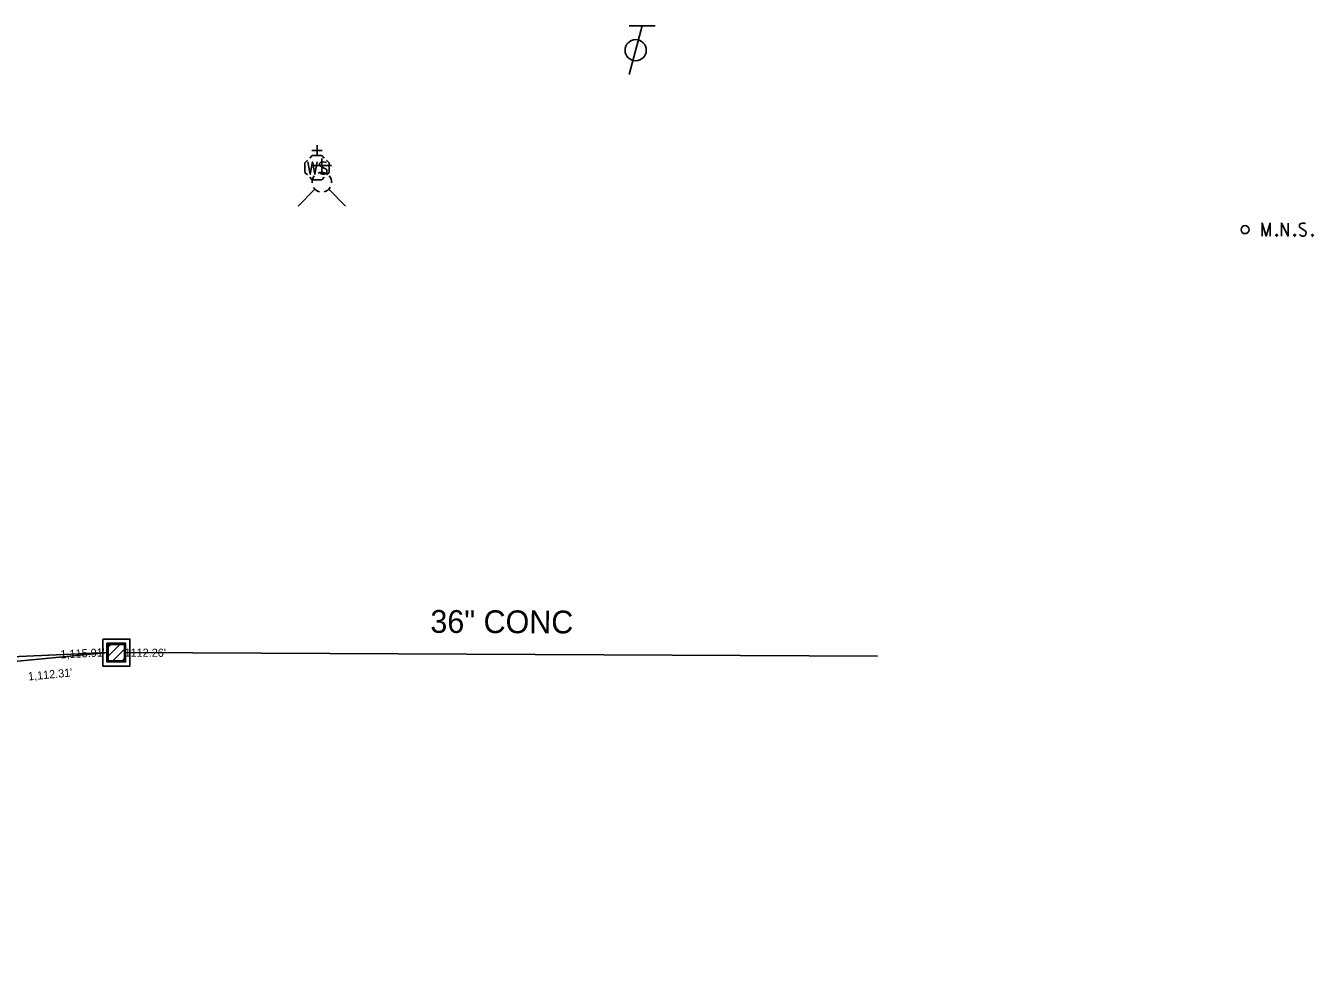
# Model space of a CAD drawing. Extents: x 146022 to 147632, y 437624 to 440659.
# Drawn here: x 147473.8 to 147632, y 438553.3 to 438669.1 of the extents above; entities that cross this region are included whole.
import ezdxf

# ---------------------------------------------------------------- set-up
doc = ezdxf.new("R2010")
doc.units = 0
for name, color, linetype in [('DR_X_Storm_Sewer', 7, 'Continuous'), ('DR_X_Text', 7, 'Continuous'), ('DT_X_Triangles', 7, 'Continuous'), ('RD_P_GR_Rt', 7, 'Continuous'), ('RW_P_Const_Limits', 7, 'Continuous'), ('SC_Scratch1', 7, 'Continuous'), ('UT_X_Electric', 7, 'Continuous'), ('UT_X_Overhead_Cable_TV', 7, 'Continuous')]:
    doc.layers.add(name, color=color, linetype=linetype)

msp = doc.modelspace()

# ---------------------------------------------------------------- linework, layer by layer
at = {"layer": 'DR_X_Storm_Sewer'}
for p, q in [((147070.7, 438553.26), (147483.94, 438592.14)), ((147428.39, 438589.62), (147483.94, 438592.14)), ((147485.94, 438592.14), (147578.45, 438591.72))]:
    msp.add_line(p, q, dxfattribs=at)
at = {"layer": 'DT_X_Triangles'}
for p, q in [((147484.94, 438593.81), (147484.94, 438593.81)), ((147483.94, 438592.14), (147483.94, 438592.14)), ((147484.94, 438593.14), (147484.94, 438593.14)), ((147484.94, 438592.14), (147484.94, 438592.14)), ((147484.94, 438592.14), (147484.94, 438592.14)), ((147484.94, 438592.14), (147484.94, 438592.14)), ((147485.94, 438592.14), (147485.94, 438592.14)), ((147484.94, 438591.14), (147484.94, 438591.14)), ((147484.94, 438590.48), (147484.94, 438590.48))]:
    msp.add_line(p, q, dxfattribs=at)
at = {"layer": 'RD_P_GR_Rt'}
for p, q in [((147510.23, 438653.81), (147508.95, 438653.81)), ((147509.59, 438653.17), (147509.59, 438654.44)), ((147511.38, 438651.96), (147508.98, 438651.96)), ((147509.59, 438651.69), (147509.59, 438651.69)), ((147510, 438651.85), (147510.7, 438651.49)), ((147510.18, 438651.1), (147510.18, 438652.82)), ((147509.34, 438649.05), (147507.26, 438646.97)), ((147510.18, 438649.9), (147510.18, 438649.9)), ((147510.18, 438649.9), (147510.18, 438649.9)), ((147511.03, 438649.05), (147513.11, 438646.97))]:
    msp.add_line(p, q, dxfattribs=at)
for points in [[(147508.42, 438652.59), (147508.11, 438652.28), (147508.11, 438651.1), (147508.41, 438650.8)], [(147508.48, 438652.4), (147508.77, 438650.87), (147509.05, 438652.4), (147509.33, 438650.87), (147509.62, 438652.4)], [(147510.49, 438652.87), (147510.18, 438653.17), (147509, 438653.17), (147508.7, 438652.87)], [(147510.77, 438650.8), (147511.07, 438651.1), (147511.07, 438652.28), (147510.77, 438652.59)], [(147508.69, 438650.52), (147509, 438650.21), (147510.18, 438650.21), (147510.49, 438650.51)]]:
    msp.add_lwpolyline(points, dxfattribs=at)
for centre, radius, start, end in [((147510.15, 438652.08), 0.271, 126.2587, 236.3676), ((147510.37, 438651.6), 0.8, 61.3463, 118.6537), ((147510.18, 438649.9), 1.2, 140.021, 184.0629), ((147510.18, 438649.9), 1.2, 68.1395, 112.038), ((147510.34, 438651.51), 0.633, 223.6695, 304.3963), ((147510.47, 438651.24), 0.339, 311.4883, 47.9358), ((147510.18, 438649.9), 1.2, 356.0165, 39.9889), ((147510.18, 438649.9), 1.2, 211.8788, 255.8479), ((147510.18, 438649.9), 1.2, 283.8239, 329.9097)]:
    msp.add_arc(centre, radius, start, end, dxfattribs=at)
at = {"layer": 'RW_P_Const_Limits'}
for points in [[(147625.68, 438643.28), (147625.68, 438644.88), (147626.19, 438643.28), (147626.67, 438644.88), (147626.67, 438643.28)], [(147628.05, 438643.28), (147628.05, 438644.88), (147628.88, 438643.28), (147628.88, 438644.88)], [(147631.03, 438644.77), (147631, 438644.79), (147630.97, 438644.82), (147630.87, 438644.86), (147630.75, 438644.88), (147630.66, 438644.88), (147630.63, 438644.88), (147630.49, 438644.84), (147630.37, 438644.77), (147630.29, 438644.67), (147630.27, 438644.57), (147630.27, 438644.49), (147630.29, 438644.39), (147630.38, 438644.3), (147630.98, 438643.93), (147631.04, 438643.87), (147631.06, 438643.82), (147631.08, 438643.75), (147631.08, 438643.67), (147631.07, 438643.6), (147631.06, 438643.55), (147631.04, 438643.48), (147631.02, 438643.43), (147630.99, 438643.4), (147630.96, 438643.36), (147630.93, 438643.33), (147630.88, 438643.31), (147630.85, 438643.3), (147630.75, 438643.28), (147630.6, 438643.28), (147630.5, 438643.31), (147630.35, 438643.4), (147630.27, 438643.47)], [(147627.44, 438643.5), (147627.5, 438643.5), (147627.53, 438643.47), (147627.57, 438643.42), (147627.57, 438643.36), (147627.53, 438643.31), (147627.5, 438643.28), (147627.44, 438643.28), (147627.41, 438643.31), (147627.38, 438643.36), (147627.38, 438643.42), (147627.41, 438643.47), (147627.44, 438643.5)], [(147629.66, 438643.5), (147629.71, 438643.5), (147629.75, 438643.47), (147629.78, 438643.42), (147629.78, 438643.36), (147629.75, 438643.31), (147629.71, 438643.28), (147629.66, 438643.28), (147629.63, 438643.31), (147629.59, 438643.36), (147629.59, 438643.42), (147629.63, 438643.47), (147629.66, 438643.5)], [(147631.84, 438643.5), (147631.9, 438643.5), (147631.93, 438643.47), (147631.96, 438643.42), (147631.96, 438643.36), (147631.93, 438643.31), (147631.9, 438643.28), (147631.84, 438643.28), (147631.81, 438643.31), (147631.78, 438643.36), (147631.78, 438643.42), (147631.81, 438643.47), (147631.84, 438643.5)]]:
    msp.add_lwpolyline(points, dxfattribs=at)
msp.add_circle((147623.59, 438644.08), 0.497, dxfattribs=at)
at = {"layer": 'UT_X_Electric'}
for p, q in [((147483.79, 438591.53), (147485.55, 438593.29)), ((147483.79, 438592.66), (147484.42, 438593.29)), ((147484.39, 438591), (147486.08, 438592.69)), ((147485.52, 438591), (147486.08, 438591.56))]:
    msp.add_line(p, q, dxfattribs=at)
for points in [[(147483.27, 438593.81), (147486.6, 438593.81), (147486.6, 438590.48), (147483.27, 438590.48)], [(147483.79, 438593.29), (147486.08, 438593.29), (147486.08, 438591), (147483.79, 438591)], [(147483.94, 438593.14), (147485.94, 438593.14), (147485.94, 438591.14), (147483.94, 438591.14)]]:
    msp.add_lwpolyline(points, close=True, dxfattribs=at)
at = {"layer": 'UT_X_Overhead_Cable_TV'}
for p, q in [((147551.13, 438669.11), (147547.93, 438669.11)), ((147549.53, 438669.11), (147547.93, 438663.11))]:
    msp.add_line(p, q, dxfattribs=at)
msp.add_circle((147548.73, 438666.11), 1.3, dxfattribs=at)

# ---------------------------------------------------------------- texts
at = {"layer": 'DR_X_Text'}
msp.add_text('36" CONC', height=2.8, rotation=359.7394, dxfattribs=at).set_placement((147523.51, 438594.57))
at = {"layer": 'SC_Scratch1'}
for s, rotation, p in [("1,115.91'", 2.6015, (147478.1, 438591.43)), ("1112.26'", 359.7394, (147485.94, 438591.64)), ("1,112.31'", 5.3754, (147474.14, 438588.71))]:
    msp.add_text(s, height=1, rotation=rotation, dxfattribs=at).set_placement(p)

doc.saveas('drawing.dxf')
